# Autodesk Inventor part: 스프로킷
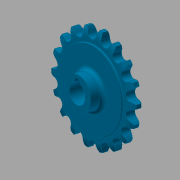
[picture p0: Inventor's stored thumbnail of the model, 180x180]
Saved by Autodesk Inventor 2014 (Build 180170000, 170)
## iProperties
Created: 2016-03
Part Number: 스프로킷
Material: 강철, 탄소
Document SubType Name: Modeling
Designer: mduedu
Density: 7.87 g/cm^3
Mass: 301.818 g
Surface Area: 124.882 cm^2
Volume: 38.3505 cm^3
Appearance: 하늘색 중간
Author: mduedu
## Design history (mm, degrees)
sketch "스케치1"
  geometry: L1 (0, 5)-(29.5, 5); L2 (29.5, 5)-(29.5, 4.1); L3 (30, 3.6)-(33.625, 3.6); L4 (40, 2)-(40, 0); L5 (40, 0)-(0, 0); L6 (0, 0)-(0, 5); L7 (0, -5)-(29.5, -5); L8 (29.5, -5)-(29.5, -4.1); L9 (30, -3.6)-(33.625, -3.6); L10 (40, -2)-(40, 0); L11 (0, 0)-(0, -5); A1 r 13.5 centre (33.625, -9.9) between (40, 2) and (33.625, 3.6); A2 r 13.5 centre (33.625, 9.9) between (33.625, -3.6) and (40, -2); A3 r 0.5 centre (30, 4.1) between (29.5, 4.1) and (30, 3.6); A4 r 0.5 centre (30, -4.1) between (30, -3.6) and (29.5, -4.1); 2 further points
  constraints: 22 end point, 8 point on circle, 6 symmetric about line, 5 tangent, 4 centre point, 4 parallel, 4 point on line, 1 equal radius, 1 horizontal, 1 perpendicular, 1 other
  dimensions: "d0" = 80 diameter of L4 L6; "d2" = 59 diameter of L2 L6; "d3" = 1.6 vertical distance of L4.start L3.end; "d4" = 3.6 distance from line of L4.end L3; "d5" = 5 distance between parallel lines of L5 L1; "d6" = 13.5 radius of A1; "d15" = 0.5 radius of A3
revolve "회전1" sketch "스케치1" stored, may be unused: angle "d7" = 90 deg
sketch "스케치2" dims "d8" = 65.2, "d11" = 80
  geometry: L1 (0, 0)-(0, 32.6); A1 r 36.57 centre (0, 0) between (-16.231, 32.771) and (0, 36.57); A2 r 3.97 centre (0, 36.57) between (-3.866, 35.665) and (0, 32.6); A3 r 12.7 centre (-16.231, 32.771) between (-3.866, 35.665) and (-5.534, 39.615); A4 r 12.7 centre (16.231, 32.771) between (5.534, 39.615) and (3.866, 35.665); A5 r 3.97 centre (0, 36.57) between (0, 32.6) and (3.866, 35.665); A6 r 40 centre (0, 0) between (5.534, 39.615) and (-5.534, 39.615); 2 further points
  constraints: 12 point on circle, 6 centre point, 4 coincident, 3 symmetric about line, 2 end point, 1 point on line, 1 tangent, 1 vertical, 1 vertical alignment, 7 other
  dimensions: "d10" = 73.14 diameter of A1; "d12" = 12.7 radius of A3
extrude "돌출1" cut sketch "스케치2" stored distance "d13" = 10; taper "d14" = 0 deg
sketch "스케치3"
  geometry: C1 r 12.5 at (0, 0); 1 further point
  constraints: 1 centre point, 1 coincident
  dimensions: "d19" = 25 diameter of C1
extrude "돌출2" join sketch "스케치3" distance "d20" = 10; taper "d21" = 0 deg
fillet "모깎기1" dims "d22" = 3
sketch "스케치4"
  geometry: L1 (-2.5, 0)-(2.5, 0); L2 (2.5, 0)-(2.5, 9.8); L3 (2.5, 9.8)-(-2.5, 9.8); L4 (-2.5, 9.8)-(-2.5, 0); C1 r 7.5 at (0, 0); 2 further points
  constraints: 8 end point, 2 coincident, 2 parallel, 1 centre point, 1 horizontal, 1 midpoint, 1 perpendicular
  dimensions: "d23" = 15 diameter of C1; "d25" = 5 distance of L2.end L3.end; "d26" = 9.8 distance of L1.end L2.end
extrude "돌출3" cut sketch "스케치4" stored distance "d27" = 8; taper "d28" = 0 deg
node "솔리드1"
pattern_circular "원형 패턴1" dims angle "d17" = 360 deg
